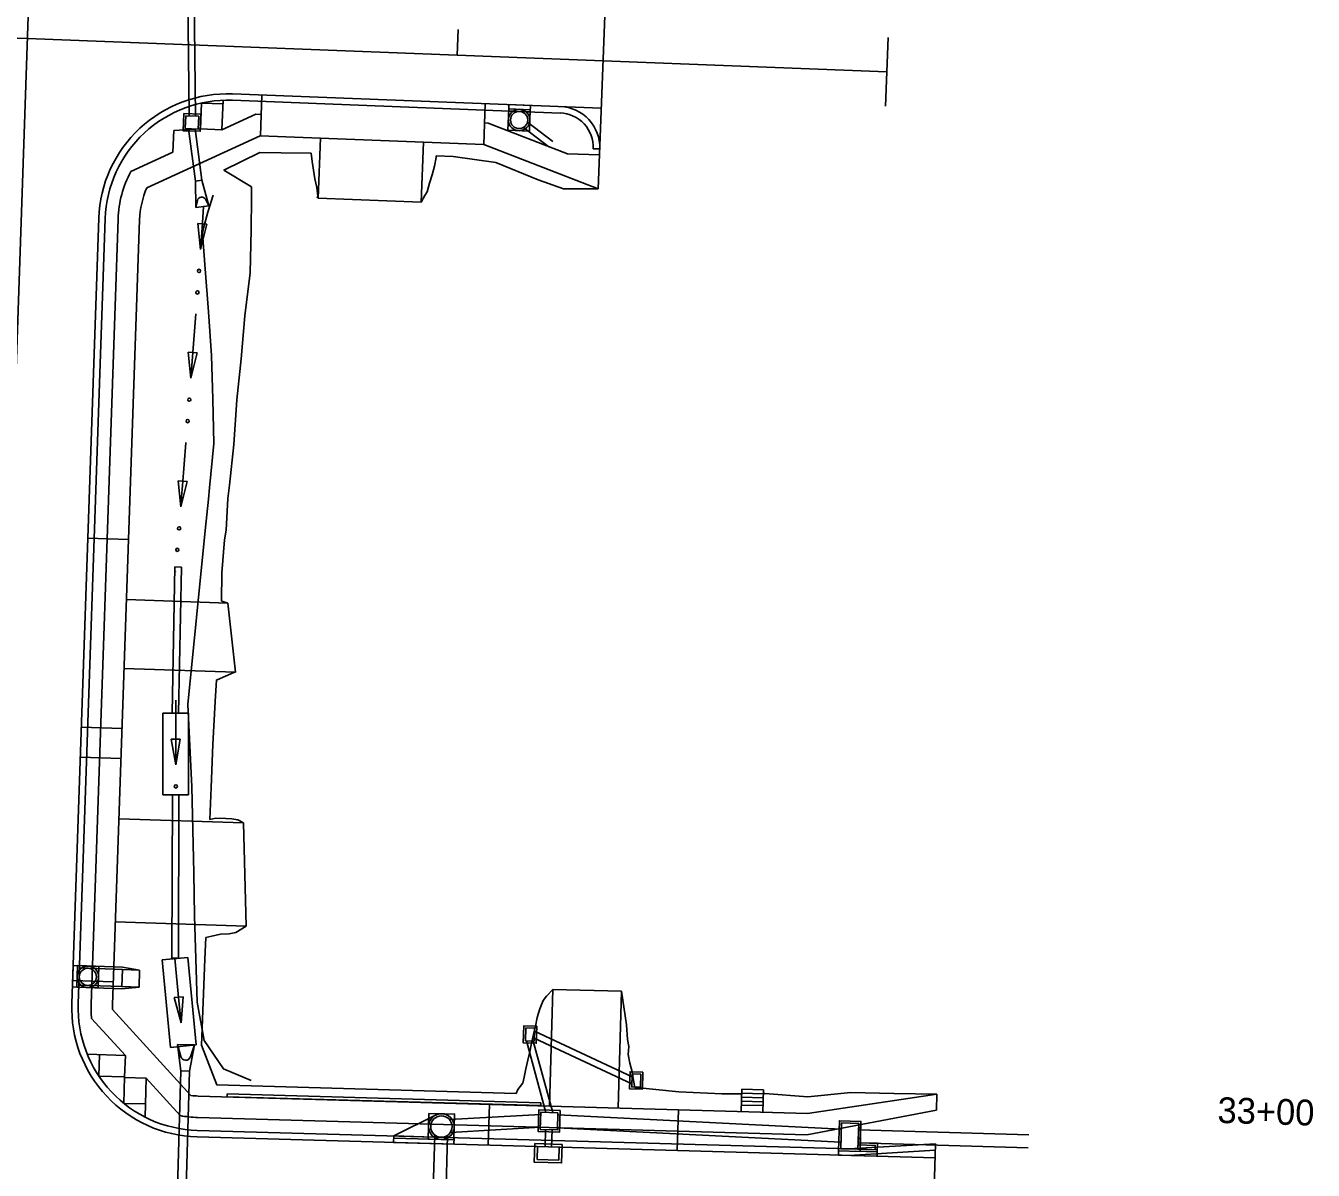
# Model space of a CAD drawing. Extents: x 979959 to 994833, y 1835619 to 1845316.
# Drawn here: x 992488.3 to 992787.8, y 1842883.2 to 1843149.5 of the extents above; entities that cross this region are included whole.
import ezdxf

# ---------------------------------------------------------------- set-up
doc = ezdxf.new("R2010")
doc.units = 0
for name, color, linetype in [('Concrete Walk Type Special', 7, 'Continuous'), ('Future 5 Lane Construction Limits', 7, 'Continuous'), ('R_Drainage', 7, 'Continuous'), ('R_Horz Alg', 7, 'Continuous'), ('R_Horz Alg Stationing', 7, 'Continuous'), ('R_Proposed Const Limits', 7, 'Continuous'), ('R_Proposed Road', 7, 'Continuous'), ('R_Special Ditch', 7, 'Continuous')]:
    doc.layers.add(name, color=color, linetype=linetype)

msp = doc.modelspace()

# ---------------------------------------------------------------- linework, layer by layer
at = {"layer": 'Concrete Walk Type Special'}
for p, q in [((992535.16, 1842901), (992535.14, 1842900.33)), ((992535.14, 1842900.33), (992608.11, 1842898.25)), ((992535.16, 1842901), (992608.13, 1842898.92)), ((992608.13, 1842898.92), (992608.11, 1842898.25))]:
    msp.add_line(p, q, dxfattribs=at)
at = {"layer": 'Future 5 Lane Construction Limits'}
for points in [[(992529.43, 1843101.14), (992529.62, 1843102.41), (992530.62, 1843106.08), (992531.91, 1843110.08)], [(992525.96, 1842991.61), (992530.04, 1843032.02), (992530.79, 1843039.37), (992531.06, 1843042.01), (992532, 1843052.3), (992531.77, 1843062.6), (992531.51, 1843072.74), (992530.78, 1843082.9), (992530, 1843092.93), (992529.43, 1843101.14)], [(992540.73, 1842904.12), (992534.25, 1842906.78), (992529.81, 1842913.4), (992528.18, 1842922.35), (992527.81, 1842932.37), (992527.57, 1842942.39), (992527.4, 1842952.4), (992527.13, 1842962.41), (992526.89, 1842972.43), (992525.96, 1842991.61)]]:
    msp.add_lwpolyline(points, dxfattribs=at)
at = {"layer": 'R_Drainage'}
for p, q in [((992525.83, 1843167.95), (992526.27, 1843128.53)), ((992527.33, 1843167.97), (992527.77, 1843128.47)), ((992604.97, 1843127.03), (992610.86, 1843122.55)), ((992526.14, 1843125.54), (992527.8, 1843113.34)), ((992527.66, 1843125.48), (992529.28, 1843113.54)), ((992605.45, 1843124.97), (992600.45, 1843125.16)), ((992604.06, 1843125.84), (992609.95, 1843121.35)), ((992527.8, 1843113.34), (992529.28, 1843113.54)), ((992527.8, 1843113.34), (992527.87, 1843107.22)), ((992529.28, 1843113.54), (992530.85, 1843107.62)), ((992528.21, 1843108.86), (992527.87, 1843107.22)), ((992530.09, 1843109.11), (992530.85, 1843107.62)), ((992527.87, 1843107.22), (992530.85, 1843107.62)), ((992522.33, 1842989.58), (992523, 1843023.58)), ((992523, 1843023.58), (992524.5, 1843023.55)), ((992523.83, 1842989.55), (992524.5, 1843023.55)), ((992526.17, 1842989.55), (992520.17, 1842989.55)), ((992523.83, 1842989.55), (992522.33, 1842989.58)), ((992526.15, 1842970.54), (992520.15, 1842970.55)), ((992522.3, 1842932.55), (992522.42, 1842970.55)), ((992523.92, 1842970.54), (992522.42, 1842970.55)), ((992523.8, 1842932.54), (992523.92, 1842970.54)), ((992525.97, 1842932.74), (992520, 1842932.16)), ((992520, 1842932.16), (992521.95, 1842911.78)), ((992523.8, 1842932.54), (992522.3, 1842932.55)), ((992525.97, 1842932.74), (992527.93, 1842912.36)), ((992500.81, 1842930.79), (992499.31, 1842930.84)), ((992500.13, 1842925.81), (992500.31, 1842930.81)), ((992500.31, 1842930.81), (992510.8, 1842930.44)), ((992500.65, 1842926.29), (992500.79, 1842930.29)), ((992500.79, 1842930.29), (992510.78, 1842929.94)), ((992505.3, 1842930.64), (992505.13, 1842925.64)), ((992510.64, 1842925.94), (992510.78, 1842929.94)), ((992514.78, 1842929.8), (992510.78, 1842929.94)), ((992514.78, 1842929.8), (992510.8, 1842930.44)), ((992514.64, 1842925.8), (992514.78, 1842929.8)), ((992500.13, 1842925.81), (992510.62, 1842925.44)), ((992500.65, 1842926.29), (992510.64, 1842925.94)), ((992510.62, 1842925.44), (992514.64, 1842925.8)), ((992514.64, 1842925.8), (992510.64, 1842925.94)), ((992629.27, 1842903.29), (992606.56, 1842913.94)), ((992629.31, 1842904.93), (992606.6, 1842915.58)), ((992527.93, 1842912.36), (992521.95, 1842911.78)), ((992527.55, 1842912.38), (992523.55, 1842912.5)), ((992524.37, 1842906.35), (992523.55, 1842912.5)), ((992523.55, 1842912.5), (992524.36, 1842909.67)), ((992526.37, 1842906.29), (992527.55, 1842912.38)), ((992527.55, 1842912.38), (992526.58, 1842909.6)), ((992604.75, 1842913.31), (992609.29, 1842896.68)), ((992606.32, 1842913.27), (992610.86, 1842896.64)), ((992522.37, 1842836.25), (992524.37, 1842906.35)), ((992526.37, 1842906.29), (992524.37, 1842906.35)), ((992524.37, 1842836.19), (992526.37, 1842906.29)), ((992573.9, 1842891.18), (992583.62, 1842896.05)), ((992608.06, 1842896.22), (992586.88, 1842894.98)), ((992677.99, 1842892.77), (992612.06, 1842896.1)), ((992607.98, 1842893.21), (992587.05, 1842891.99)), ((992677.9, 1842889.77), (992611.98, 1842893.1)), ((992573.89, 1842890.68), (992587.88, 1842890.28)), ((992583.41, 1842891.41), (992582.38, 1842855.42)), ((992586.41, 1842891.33), (992585.38, 1842855.34)), ((992609.1, 1842888.68), (992609.21, 1842892.68)), ((992610.6, 1842888.64), (992610.71, 1842892.64)), ((992721.57, 1842891.46), (992681.98, 1842892.61)), ((992721.48, 1842888.46), (992681.9, 1842889.61))]:
    msp.add_line(p, q, dxfattribs=at)
for points in [[(992605.45, 1843124.97), (992600.45, 1843125.16), (992600.64, 1843130.16), (992605.64, 1843129.96)], [(992605.62, 1843129.46), (992600.62, 1843129.66), (992600.68, 1843131.16), (992605.68, 1843130.96)], [(992525.04, 1843129.08), (992524.88, 1843125.08), (992528.88, 1843124.93), (992529.04, 1843128.93)], [(992525.52, 1843128.56), (992525.4, 1843125.56), (992528.4, 1843125.45), (992528.52, 1843128.45)], [(992500.8, 1842930.79), (992500.63, 1842925.79), (992499.13, 1842925.85), (992499.31, 1842930.84)], [(992505.3, 1842930.64), (992505.13, 1842925.64), (992500.13, 1842925.81), (992500.3, 1842930.81)], [(992607.14, 1842916.75), (992604.14, 1842916.83), (992604.02, 1842912.83), (992607.02, 1842912.75)], [(992606.62, 1842916.26), (992604.62, 1842916.32), (992604.54, 1842913.32), (992606.54, 1842913.26)], [(992631.85, 1842906.04), (992628.85, 1842906.12), (992628.73, 1842902.13), (992631.73, 1842902.04)], [(992631.33, 1842905.55), (992629.33, 1842905.61), (992629.25, 1842902.61), (992631.25, 1842902.55)], [(992582.05, 1842896.45), (992588.05, 1842896.28), (992587.88, 1842890.28), (992581.88, 1842890.45)], [(992612.59, 1842897.09), (992607.59, 1842897.23), (992607.45, 1842892.23), (992612.45, 1842892.09)], [(992612.08, 1842896.6), (992608.08, 1842896.72), (992607.96, 1842892.72), (992611.96, 1842892.6)], [(992682.54, 1842894.59), (992677.54, 1842894.73), (992677.34, 1842887.74), (992682.34, 1842887.59)], [(992682.03, 1842894.11), (992678.03, 1842894.22), (992677.86, 1842888.22), (992681.85, 1842888.11)], [(992573.9, 1842891.18), (992587.9, 1842890.78), (992587.85, 1842889.28), (992573.86, 1842889.68)], [(992613.04, 1842889.24), (992606.71, 1842889.42), (992606.58, 1842885.08), (992612.91, 1842884.9)], [(992612.35, 1842888.59), (992607.35, 1842888.73), (992607.27, 1842885.73), (992612.27, 1842885.59)], [(992686.35, 1842887.98), (992677.36, 1842888.24), (992677.31, 1842886.74), (992686.31, 1842886.48)]]:
    msp.add_lwpolyline(points, close=True, dxfattribs=at)
for points in [[(992520.17, 1842989.58), (992520.16, 1842982.56), (992520.15, 1842970.55)], [(992526.17, 1842989.55), (992526.16, 1842982.56), (992526.15, 1842970.54)], [(992499.31, 1842930.84), (992499.13, 1842925.85), (992500.63, 1842925.79), (992500.81, 1842930.79)], [(992682.4, 1842889.59), (992682.54, 1842894.59), (992677.54, 1842894.73), (992677.34, 1842887.74), (992682.34, 1842887.59)], [(992681.88, 1842889.11), (992682.03, 1842894.11), (992678.03, 1842894.22), (992677.86, 1842888.22), (992681.85, 1842888.11)], [(992681.34, 1842887.62), (992686.34, 1842887.48), (992686.4, 1842889.48), (992682.4, 1842889.59)], [(992681.85, 1842888.11), (992685.85, 1842887.99), (992685.88, 1842888.99), (992681.88, 1842889.11)]]:
    msp.add_lwpolyline(points, dxfattribs=at)
for centre, radius in [((992603.04, 1843127.56), 2.5), ((992603.04, 1843127.56), 2.5), ((992603.04, 1843127.56), 2), ((992603.04, 1843127.56), 2), ((992502.72, 1842928.22), 2.5), ((992502.72, 1842928.22), 2.5), ((992502.72, 1842928.22), 2), ((992502.72, 1842928.22), 2), ((992584.97, 1842893.37), 3), ((992584.97, 1842893.37), 3), ((992584.97, 1842893.37), 2.5), ((992584.97, 1842893.37), 2.5)]:
    msp.add_circle(centre, radius, dxfattribs=at)
for centre, radius, start, end in [((992529.19, 1843108.65), 1, 27.0898, 168.3757), ((992525.48, 1842909.98), 1.17, 195.7723, 340.7125)]:
    msp.add_arc(centre, radius, start, end, dxfattribs=at)
at = {"layer": 'R_Horz Alg'}
for p, q in [((992476.02, 1842777.04), (992513.51, 1843870.41)), ((992288.84, 1843154.22), (992488.69, 1843146.49)), ((992488.69, 1843146.49), (992688.54, 1843138.77))]:
    msp.add_line(p, q, dxfattribs=at)
at = {"layer": 'R_Horz Alg Stationing'}
for points in [[(992588.85, 1843148.63), (992588.61, 1843142.63)], [(992688.85, 1843146.76), (992688.23, 1843130.77)]]:
    msp.add_lwpolyline(points, dxfattribs=at)
at = {"layer": 'R_Proposed Const Limits'}
for points in [[(992540.79, 1843112.03), (992534.37, 1843115.91), (992542.74, 1843119.98), (992547.71, 1843119.92), (992554.68, 1843119.86)], [(992554.68, 1843119.86), (992554.87, 1843117.92), (992555.2, 1843115.9), (992555.56, 1843113.89), (992556.01, 1843111.87), (992556.19, 1843109.86)], [(992583.78, 1843119.19), (992583.78, 1843118.8), (992583.35, 1843116.82), (992582.79, 1843114.84), (992582.21, 1843112.86), (992581.65, 1843110.88), (992581.12, 1843109.98), (992580.29, 1843108.43)], [(992583.78, 1843119.19), (992587.7, 1843119.04), (992597.66, 1843117.65), (992607.51, 1843113.64), (992613.33, 1843111.55), (992621.44, 1843111.51)], [(992533.8, 1843015.61), (992533.86, 1843022.22), (992534.54, 1843029.92), (992534.9, 1843032.16), (992535.32, 1843039.49), (992535.65, 1843042.58), (992536.7, 1843052.07), (992537.37, 1843062.47), (992538.37, 1843072.03), (992539.27, 1843082.03), (992540.5, 1843092.03), (992540.69, 1843102.03), (992540.77, 1843109.44), (992540.77, 1843109.77), (992540.78, 1843110.16), (992540.79, 1843112.03)], [(992556.19, 1843109.86), (992556.04, 1843109.37)], [(992533.8, 1843015.61), (992533.89, 1843015.61), (992534.57, 1843015.42), (992535.26, 1843015.16)], [(992532.64, 1842997.32), (992532.81, 1842997.32), (992536.66, 1842998.98), (992537.1, 1842999.09)], [(992531.12, 1842964.78), (992531.41, 1842972.27), (992531.82, 1842982.26), (992532.35, 1842992.25), (992532.64, 1842997.32)], [(992531.12, 1842964.78), (992532.5, 1842965.12), (992534.85, 1842965.05), (992536.21, 1842965.01), (992537.61, 1842964.77), (992538.95, 1842964.01)], [(992530.14, 1842937.34), (992531.56, 1842937.69), (992533.58, 1842938.13), (992535.58, 1842938.21), (992537.12, 1842938.51), (992539.58, 1842939.97)], [(992529.14, 1842912.31), (992529.55, 1842922.31), (992529.94, 1842932.3), (992530.14, 1842937.34)], [(992603.87, 1842903.44), (992604.19, 1842904.83), (992604.63, 1842906.81), (992605.07, 1842908.8), (992605.51, 1842910.79), (992605.95, 1842912.78), (992606.39, 1842914.77), (992606.82, 1842916.76), (992607.26, 1842918.74), (992607.89, 1842920.73), (992608.65, 1842922.71), (992609.38, 1842923.68), (992610.88, 1842925.29)], [(992629.94, 1842902.48), (992629.66, 1842904.1), (992629.31, 1842906.11), (992628.83, 1842908.13), (992628.37, 1842910.14), (992628.54, 1842912.01), (992628.24, 1842913.64), (992628.05, 1842917.02), (992626.88, 1842924.84)], [(992529.14, 1842912.31), (992532.74, 1842903.07), (992602.35, 1842901.08)], [(992602.35, 1842901.08), (992602.72, 1842902), (992603.8, 1842903.38), (992603.87, 1842903.44)], [(992629.94, 1842902.48), (992630.24, 1842902.44), (992640.22, 1842901.47), (992650.21, 1842900.99), (992654.82, 1842901.02)], [(992659.83, 1842901.06), (992660.21, 1842901.06), (992670.2, 1842900.3), (992680.23, 1842901.29), (992690.23, 1842901.05), (992700.23, 1842900.88)]]:
    msp.add_lwpolyline(points, dxfattribs=at)
at = {"layer": 'R_Proposed Road'}
for p, q in [((992623.07, 1843153.81), (992621.44, 1843111.51)), ((992536.41, 1843133.64), (992622.16, 1843130.33)), ((992542.86, 1843123.88), (992543.22, 1843133.38)), ((992529.14, 1843131.5), (992528.91, 1843125.51)), ((992534.11, 1843131.31), (992529.14, 1843131.5)), ((992534.17, 1843132.14), (992533.91, 1843125.31)), ((992536.35, 1843132.14), (992612.61, 1843129.19)), ((992594.82, 1843121.88), (992595.18, 1843131.37)), ((992541.79, 1843128.93), (992533.91, 1843125.31)), ((992541.79, 1843128.93), (992543.05, 1843128.88)), ((992595.01, 1843126.87), (992595.85, 1843126.84)), ((992595.85, 1843126.84), (992614.26, 1843119.67)), ((992542.79, 1843123.89), (992516.43, 1843111.79)), ((992522.52, 1843120.09), (992522.71, 1843125.09)), ((992528.91, 1843125.51), (992522.71, 1843125.09)), ((992533.88, 1843125.31), (992528.91, 1843125.51)), ((992542.79, 1843123.89), (992594.82, 1843121.88)), ((992556.31, 1843109.35), (992556.85, 1843123.34)), ((992580.29, 1843108.43), (992580.83, 1843122.42)), ((992594.82, 1843121.88), (992621.44, 1843111.51)), ((992620.3, 1843120.89), (992621.8, 1843120.83)), ((992522.52, 1843120.09), (992512.71, 1843115.59)), ((992614.26, 1843119.67), (992621.74, 1843119.45)), ((992556.31, 1843109.35), (992580.29, 1843108.43)), ((992499, 1842922), (992505.27, 1843104.69)), ((992500.5, 1842921.95), (992506.77, 1843104.64)), ((992503.5, 1842921.85), (992509.76, 1843104.54)), ((992508.5, 1842921.67), (992514.76, 1843104.37)), ((992512.21, 1843029.96), (992502.72, 1843030.29)), ((992535.26, 1843015.16), (992511.73, 1843015.97)), ((992535.26, 1843015.16), (992537.1, 1842999.09)), ((992537.1, 1842999.09), (992511.18, 1842999.98)), ((992510.7, 1842985.99), (992501.21, 1842986.31)), ((992500.97, 1842979.32), (992510.46, 1842978.99)), ((992509.98, 1842965), (992538.95, 1842964.01)), ((992538.95, 1842964.01), (992539.58, 1842939.97)), ((992509.16, 1842941.02), (992539.58, 1842939.97)), ((992499.19, 1842927.35), (992508.68, 1842927.02)), ((992610.88, 1842925.29), (992610.11, 1842898.15)), ((992610.88, 1842925.29), (992626.88, 1842924.84)), ((992626.88, 1842924.84), (992626.1, 1842897.7)), ((992508.49, 1842920.61), (992526.72, 1842900.6)), ((992503.6, 1842918.55), (992511.46, 1842909.92)), ((992502.59, 1842910.22), (992511.46, 1842909.92)), ((992505.47, 1842910.12), (992505.3, 1842905.13)), ((992511.46, 1842909.92), (992511.29, 1842904.92)), ((992505.3, 1842905.13), (992511.29, 1842904.92)), ((992511.12, 1842898.77), (992511.29, 1842904.92)), ((992516.29, 1842904.62), (992511.29, 1842904.77)), ((992516.03, 1842895.59), (992516.29, 1842904.62)), ((992516.29, 1842904.62), (992524.21, 1842895.92)), ((992654.71, 1842896.88), (992654.85, 1842902.05)), ((992654.85, 1842902.05), (992659.85, 1842901.91)), ((992659.7, 1842896.74), (992659.85, 1842901.91)), ((992516.11, 1842898.63), (992511.12, 1842898.77)), ((992528.4, 1842900.48), (992670.09, 1842896.45)), ((992654.78, 1842899.3), (992659.77, 1842899.16)), ((992654.8, 1842900.22), (992659.8, 1842900.07)), ((992654.83, 1842901.13), (992659.83, 1842900.99)), ((992700.23, 1842900.88), (992670.09, 1842896.45)), ((992700.12, 1842897.19), (992700.23, 1842900.88)), ((992596.12, 1842898.55), (992595.85, 1842889.06)), ((992640.1, 1842897.3), (992639.83, 1842887.8)), ((992654.75, 1842898.38), (992659.75, 1842898.24)), ((992669.94, 1842891.45), (992700.12, 1842897.19)), ((992528.26, 1842895.48), (992669.94, 1842891.45)), ((992528.13, 1842890.98), (992699.8, 1842886.1)), ((992528.17, 1842892.48), (992679.86, 1842888.17)), ((992679.72, 1842888.16), (992699.9, 1842889.37)), ((992679.81, 1842886.67), (992699.85, 1842887.86)), ((992698.6, 1842843.61), (992699.9, 1842889.37))]:
    msp.add_line(p, q, dxfattribs=at)
for centre, radius, start, end in [((992535.25, 1843103.66), 30, 87.7861, 178.0361), ((992535.25, 1843103.66), 28.5, 87.7861, 178.0361), ((992612.3, 1843121.2), 9.5, 357.7861, 87.7861), ((992612.3, 1843121.2), 8, 357.7861, 87.7861), ((992535.25, 1843103.66), 25.5, 152.123, 178.0361), ((992535.25, 1843103.66), 20.5, 156.6364, 178.0361), ((992528.98, 1842920.97), 30, 178.0361, 268.3694), ((992528.98, 1842920.97), 28.5, 178.0361, 268.3694), ((992528.98, 1842920.97), 25.5, 178.0361, 185.4472), ((992528.98, 1842920.97), 20.5, 178.0361, 181.0117), ((992528.98, 1842920.97), 20.5, 263.6457, 268.3694), ((992528.98, 1842920.97), 25.5, 259.2102, 268.3694)]:
    msp.add_arc(centre, radius, start, end, dxfattribs=at)
at = {"layer": 'R_Special Ditch'}
for p, q in [((992530.41, 1843103.35), (992528.3, 1843103.5)), ((992528.3, 1843103.5), (992528.92, 1843097.44)), ((992528.92, 1843097.44), (992530.41, 1843103.35)), ((992528.19, 1843073.39), (992526.08, 1843073.55)), ((992526.08, 1843073.55), (992526.68, 1843067.49)), ((992526.68, 1843067.49), (992528.19, 1843073.39)), ((992525.85, 1843043.44), (992523.75, 1843043.61)), ((992523.75, 1843043.61), (992524.32, 1843037.54)), ((992524.32, 1843037.54), (992525.85, 1843043.44)), ((992524.22, 1842983.51), (992522.11, 1842983.52)), ((992522.11, 1842983.52), (992523.16, 1842977.52)), ((992523.16, 1842977.52), (992524.22, 1842983.51)), ((992524.9, 1842923.59), (992522.79, 1842923.39)), ((992522.79, 1842923.39), (992524.42, 1842917.52)), ((992524.42, 1842917.52), (992524.9, 1842923.59))]:
    msp.add_line(p, q, dxfattribs=at)
for points in [[(992529.65, 1843107.46), (992529.29, 1843102.42), (992528.92, 1843097.44)], [(992527.82, 1843082.44), (992527.06, 1843072.48), (992526.68, 1843067.49)], [(992527.82, 1843082.48), (992527.82, 1843082.46), (992527.82, 1843082.44)], [(992525.51, 1843052.49), (992524.72, 1843042.54), (992524.51, 1843039.92), (992524.32, 1843037.54)], [(992525.52, 1843052.53), (992525.51, 1843052.52), (992525.51, 1843052.49)], [(992523.09, 1843022.59), (992523.09, 1843022.59), (992523.09, 1843022.55)], [(992523.17, 1842992.52), (992523.16, 1842982.56), (992523.16, 1842977.52)], [(992523.17, 1842992.55), (992523.17, 1842992.52)], [(992523.12, 1842962.52), (992523.12, 1842962.48)], [(992522.98, 1842932.49), (992522.98, 1842932.45)], [(992522.98, 1842932.45), (992523.93, 1842922.59), (992524.42, 1842917.52)]]:
    msp.add_lwpolyline(points, dxfattribs=at)
for centre in [(992528.59, 1843092.45), (992528.22, 1843087.45), (992526.33, 1843062.49), (992525.94, 1843057.5), (992523.95, 1843032.55), (992523.54, 1843027.56), (992523.19, 1842972.51)]:
    msp.add_circle(centre, 0.375, dxfattribs=at)

# ---------------------------------------------------------------- texts
at = {"layer": 'R_Horz Alg Stationing'}
msp.add_text('33+00', height=6, rotation=358.3694, dxfattribs=at).set_placement((992765.42, 1842894.23))

doc.saveas('drawing.dxf')
